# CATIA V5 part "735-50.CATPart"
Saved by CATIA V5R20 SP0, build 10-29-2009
Part number: 735-50
Bounding box of the stored display mesh (mm): x -40 to 40, y -40 to 40, z -47 to 50
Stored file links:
  C:\Users\Utente\Desktop\IO LAVORO\3D X SITO CF\X SITO\735\735-50.CATPart
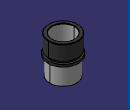
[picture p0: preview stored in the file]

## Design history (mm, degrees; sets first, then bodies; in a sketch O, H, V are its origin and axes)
Set1
  DatumSurface1 to DatumSurface25 "735-50"
Body1 (main body)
